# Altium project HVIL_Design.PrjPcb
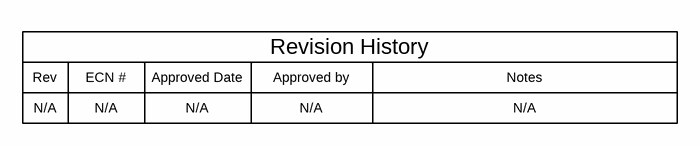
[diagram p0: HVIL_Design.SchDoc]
TID: N/A; TechSupport: http://www.ti.com/support; SCH_Rev: E1; PRJ_Title: Change in menu Project|Project Options|Parameters; PRJ_Number: TIDA-020069; PRJ_Engineer: Enter name of project lead; PRJ_Customer: Public Release; PCB_Rev: E1; PCB_Layout: Who did the Layout?; CopyrightYear: 2018
4 sheets, 99 parts. Net scope: global (net labels, ports and power ports of the same name join across sheets).
Board file: HVIL_Design.PcbDoc
Sheets:
  HVIL_Design.SchDoc
  HVIL_Design_BlankSheet.SchDoc
  HVIL_Design_Hardware.SchDoc
  HVIL_Design_Schematic.SchDoc

## Sheet HVIL_Design.SchDoc
size 431 x 279 mm; Date: Not shown in title block; ApprovedBy: Not shown in title block; CheckedBy: Not shown in title block; Author: Not shown in title block; CompanyName: Not shown in title block; Engineer: Not shown in title block; Organization: Not shown in title block; Address1: Not shown in title block; Address2: Not shown in title block; Address3: Not shown in title block; Address4: Not shown in title block; DocumentNumber: 1; Revision: Use project parameter SCH_Rev; SheetNumber: 1; SheetTotal: 4; PageSetup: Record=PageOptions¦CenterHorizontal=True¦CenterVertical=True¦PrintScale=1.00¦XCorrection=1.00¦YCorrection=1.00¦PrintKind=0¦BorderSize=5000000¦LeftOffset=0¦BottomOffset=0¦Orientation=2¦PaperLength=1000¦PaperWidth=1000¦Scale=100¦PaperSource=15¦PrintQuality=600¦MediaType=1¦DitherType=10¦PaperKind=Letter¦PrintScaleMode=1

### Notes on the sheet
- Rev
- N/A
- ECN #
- Approved Date
- Approved by
- Revision History
- Notes

## Sheet HVIL_Design_BlankSheet.SchDoc
size 431 x 279 mm; Date: Not shown in title block; ApprovedBy: Not shown in title block; CheckedBy: Not shown in title block; Author: Not shown in title block; CompanyName: Not shown in title block; Engineer: Not shown in title block; Organization: Not shown in title block; Address1: Not shown in title block; Address2: Not shown in title block; Address3: Not shown in title block; Address4: Not shown in title block; DocumentNumber: 1; Revision: Use project parameter SCH_Rev; SheetNumber: 2; SheetTotal: 4; PageSetup: Record=PageOptions¦CenterHorizontal=True¦CenterVertical=True¦PrintScale=1.00¦XCorrection=1.00¦YCorrection=1.00¦PrintKind=0¦BorderSize=5000000¦LeftOffset=0¦BottomOffset=0¦Orientation=2¦PaperLength=1000¦PaperWidth=1000¦Scale=100¦PaperSource=15¦PrintQuality=600¦MediaType=1¦DitherType=10¦PaperKind=Letter¦PrintScaleMode=1
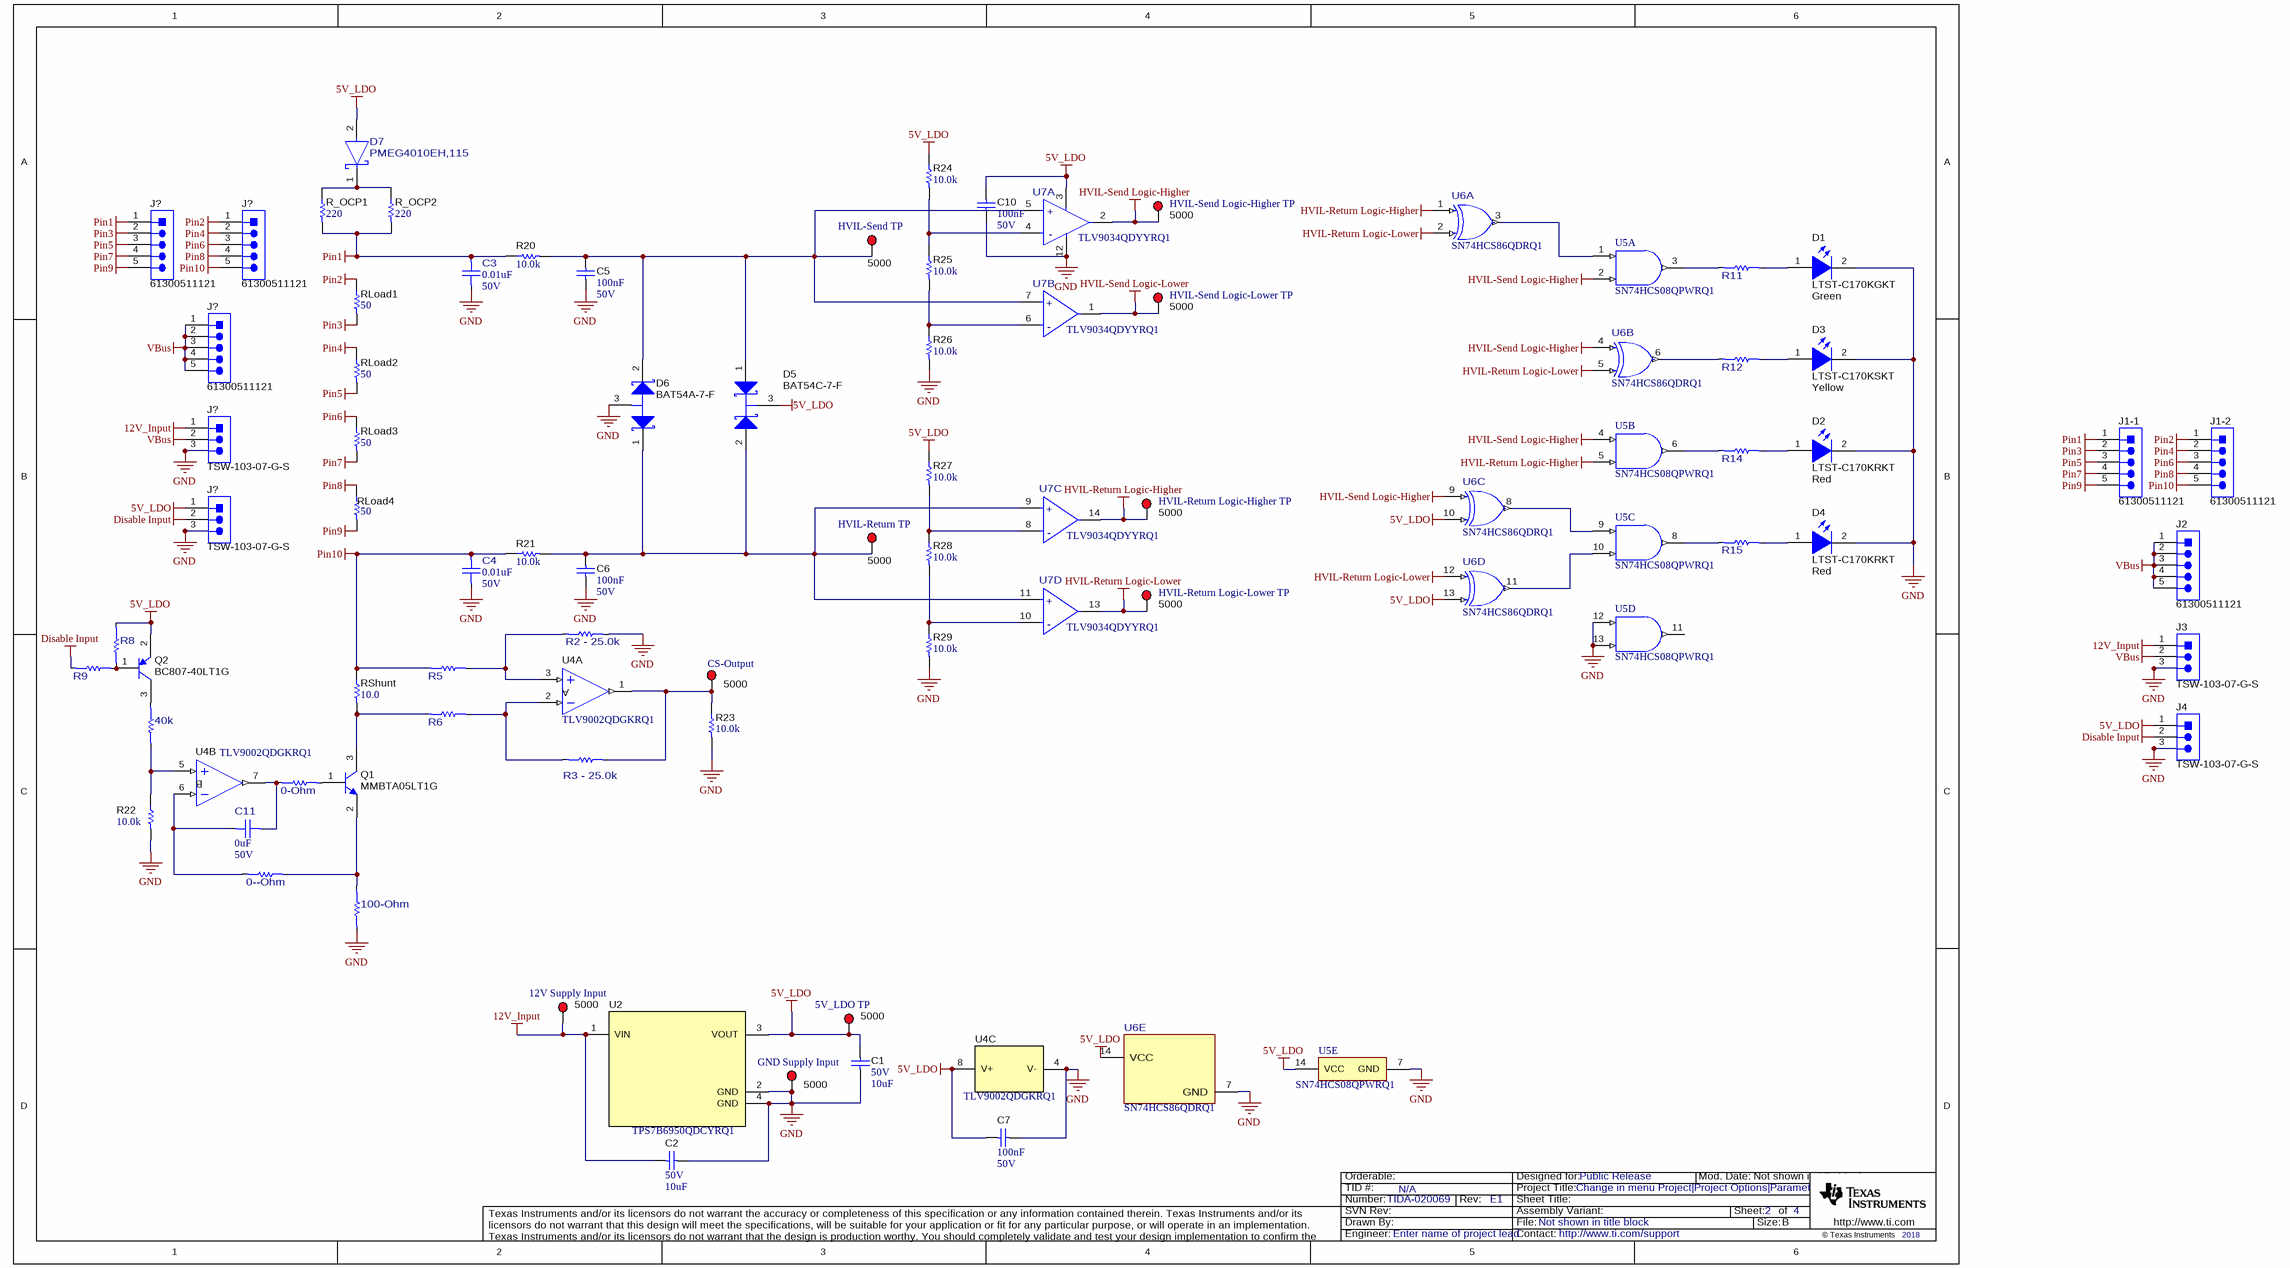
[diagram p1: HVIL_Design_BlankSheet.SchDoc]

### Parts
(Parts that share a designator on the sheet are numbered #1, #2 ... from top to bottom, then left to right.)
0--Ohm  PCAN0805E1000BST5  [FP-PCAN0805E1000BST5_0805-MFG]  (value not drawn)
0-Ohm  PCAN0805E1000BST5  [FP-PCAN0805E1000BST5_0805-MFG]  (value not drawn)
5V_LDO_TP  5000  [Keystone5000]
12V_Supply_Input  5000  [Keystone5000]
40k  PCAN0805E1001BST5  [FP-PCAN0805E1001BST5_0805-MFG]  (value not drawn)
100-Ohm  PCAN0805E1000BST5  [FP-PCAN0805E1000BST5_0805-MFG]  (value not drawn)
C1  VDC_V: 50V  ValueDisplayed: 10uF  [1206_180]  (hidden comment: CL31B106KBHNNNE)
C2  VDC_V: 50V  ValueDisplayed: 10uF  [1206_180]  (hidden comment: CL31B106KBHNNNE)
C3  ValueDisplayed: 0.01uF  VDC_V: 50V  [FP-08055F103K4T2A_0805-MFG]  (hidden comment: 08055F103K4T2A)
C4  ValueDisplayed: 0.01uF  VDC_V: 50V  [FP-08055F103K4T2A_0805-MFG]  (hidden comment: 08055F103K4T2A)
C5  Cap_F: 100nF  VDC_V: 50V  [0805_HV]  (hidden comment: GCM21BR71H104KA37K)
C6  Cap_F: 100nF  VDC_V: 50V  [0805_HV]  (hidden comment: GCM21BR71H104KA37K)
C7  Cap_F: 100nF  VDC_V: 50V  [0805_HV]  (hidden comment: GCM21BR71H104KA37K)
C10  Cap_F: 100nF  VDC_V: 50V  [0805_HV]  (hidden comment: GCM21BR71H104KA37K)
C11  ValueDisplayed: 0uF  VDC_V: 50V  [FP-08055F103K4T2A_0805-MFG]  (hidden comment: 08055F103K4T2A)
CS-Output  5000  [Keystone5000]
D1  LTST-C170KGKT  value Green  [LTST-C170KGKT_Green]
D2  LTST-C170KRKT  value Red  [LED_LTST-C170_Red]
D3  LTST-C170KSKT  value Yellow  [LED_LTST-C170]
D4  LTST-C170KRKT  value Red  [LED_LTST-C170_Red]
D5  BAT54C-7-F  [SOT-23]
D6  BAT54A-7-F  [SOT-23]
D7  PMEG4010EH,115  [FP-PMEG4010EH_115_SOD123F-MFG]
GND_Supply_Input  5000  [Keystone5000]
HVIL-Return_Logic-Higher_TP  5000  [Keystone5000]
HVIL-Return_Logic-Lower_TP  5000  [Keystone5000]
HVIL-Return_TP  5000  [Keystone5000]
HVIL-Send_Logic-Higher_TP  5000  [Keystone5000]
HVIL-Send_Logic-Lower_TP  5000  [Keystone5000]
HVIL-Send_TP  5000  [Keystone5000]
J1-1  61300511121  [Wurth_61300511121]
J1-2  61300511121  [Wurth_61300511121]
J2  61300511121  [Wurth_61300511121]
J3  TSW-103-07-G-S  [TSW-103-07-G-S]
J4  TSW-103-07-G-S  [TSW-103-07-G-S]
J?#1  61300511121  [Wurth_61300511121]
J?#2  61300511121  [Wurth_61300511121]
J?#3  61300511121  [Wurth_61300511121]
J?#4  TSW-103-07-G-S  [TSW-103-07-G-S]
J?#5  TSW-103-07-G-S  [TSW-103-07-G-S]
Q1  MMBTA05LT1G  [SOT-23]
Q2  BC807-40LT1G  [SOT-23]
R2_-_25.0k  PCAN0805E1001BST5  [FP-PCAN0805E1001BST5_0805-MFG]  (value not drawn)
R3_-_25.0k  PCAN0805E1001BST5  [FP-PCAN0805E1001BST5_0805-MFG]  (value not drawn)
R5  PCAN0805E1001BST5  [FP-PCAN0805E1001BST5_0805-MFG]  (value not drawn)
R6  PCAN0805E1001BST5  [FP-PCAN0805E1001BST5_0805-MFG]  (value not drawn)
R8  PCAN0805E1001BST5  [FP-PCAN0805E1001BST5_0805-MFG]  (value not drawn)
R9  PCAN0805E1001BST5  [FP-PCAN0805E1001BST5_0805-MFG]  (value not drawn)
R11  PCAN0805E1001BST5  [FP-PCAN0805E1001BST5_0805-MFG]  (value not drawn)
R12  PCAN0805E1001BST5  [FP-PCAN0805E1001BST5_0805-MFG]  (value not drawn)
R14  PCAN0805E1001BST5  [FP-PCAN0805E1001BST5_0805-MFG]  (value not drawn)
R15  PCAN0805E1001BST5  [FP-PCAN0805E1001BST5_0805-MFG]  (value not drawn)
R20  ValueDisplayed: 10.0k  [0805_HV]  (hidden comment: MCU0805MD1002BP100)
R21  ValueDisplayed: 10.0k  [0805_HV]  (hidden comment: MCU0805MD1002BP100)
R22  ValueDisplayed: 10.0k  [0805_HV]  (hidden comment: MCU0805MD1002BP100)
R23  ValueDisplayed: 10.0k  [0805_HV]  (hidden comment: MCU0805MD1002BP100)
R24  ValueDisplayed: 10.0k  [0805_HV]  (hidden comment: MCU0805MD1002BP100)
R25  ValueDisplayed: 10.0k  [0805_HV]  (hidden comment: MCU0805MD1002BP100)
R26  ValueDisplayed: 10.0k  [0805_HV]  (hidden comment: MCU0805MD1002BP100)
R27  ValueDisplayed: 10.0k  [0805_HV]  (hidden comment: MCU0805MD1002BP100)
R28  ValueDisplayed: 10.0k  [0805_HV]  (hidden comment: MCU0805MD1002BP100)
R29  ValueDisplayed: 10.0k  [0805_HV]  (hidden comment: MCU0805MD1002BP100)
R_OCP1  ValueDisplayed: 220  [1206]  (hidden comment: CRCW1206220RJNEA)
R_OCP2  ValueDisplayed: 220  [1206]  (hidden comment: CRCW1206220RJNEA)
RLoad1  ValueDisplayed: 50  [0603]  (hidden comment: FC0603E50R0BTBST1)
RLoad2  ValueDisplayed: 50  [0603]  (hidden comment: FC0603E50R0BTBST1)
RLoad3  ValueDisplayed: 50  [0603]  (hidden comment: FC0603E50R0BTBST1)
RLoad4  ValueDisplayed: 50  [0603]  (hidden comment: FC0603E50R0BTBST1)
RShunt  ValueDisplayed: 10.0  [0805_HV]  (hidden comment: PATT0805E10R0BGT1)
U2  TPS7B6950QDCYRQ1  [DCY0004A_N]
U4  PartNumber: TLV9002QDGKRQ1  [DGK0008A_N]  (hidden comment: TLV9002QDRQ1)  (parts A,B,C of 3)
U5  SN74HCS08QPWRQ1  [PW0014A_N]  (parts A,B,C,D,E of 5)
U6  PartNumber: SN74HCS86QDRQ1  [D0014A-MFG]  (hidden comment: SN74HCS86DR)  (parts A,B,C,D,E of 5)
U7  TLV9034QDYYRQ1  [DYY0014A-MFG]  (parts A,B,C,D of 4)

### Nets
5V_LDO: 5V_LDO_TP.1 C1.2 C7.1 C10.1 D5.3(K) D7.2(ANODE) J4.1 J?#5.1 Q2.2(E) R8.1 R24.1 R27.1 U2.3(VOUT) U4.8(V+) U5.14(VCC) U6.10(3B) U6.13(4B) U6.14(VCC) U7.3(V+)
12V_Input: 12V_Supply_Input.1 C2.2 J3.1 J?#4.1 U2.1(VIN)
Disable Input: J4.2 J?#5.2 R9.1
GND: 100-Ohm.2 C1.1 C2.1 C3.2 C4.2 C5.1 C6.1 C7.2 C10.2 D1.2(K) D2.2(K) D3.2(K) D4.2(K) D6.3(A) GND_Supply_Input.1 J3.3 J4.3 J?#4.3 J?#5.3 R2_-_25.0k.2 R22.2 R23.2 R26.2 R29.2 U2.2(GND) U2.4(GND) U4.4(V-) U5.7(GND) U5.12(4A) U5.13(4B) U6.7(GND) U7.12(V-)
HVIL-Return Logic-Higher: HVIL-Return_Logic-Higher_TP.1 U5.5(2B) U6.1(1A) U7.14(OUT3)
HVIL-Return Logic-Lower: HVIL-Return_Logic-Lower_TP.1 U6.2(1B) U6.5(2B) U6.12(4A) U7.13(OUT4)
HVIL-Send Logic-Higher: HVIL-Send_Logic-Higher_TP.1 U5.2(1B) U5.4(2A) U6.4(2A) U6.9(3A) U7.2(OUT1)
HVIL-Send Logic-Lower: HVIL-Send_Logic-Lower_TP.1 U7.1(OUT2)
Pin1: C3.1 J1-1.1 J?#1.1 R20.1 R_OCP1.2 R_OCP2.2
Pin2: J1-2.1 J?#2.1 RLoad1.1
Pin3: J1-1.2 J?#1.2 RLoad1.2
Pin4: J1-2.2 J?#2.2 RLoad2.1
Pin5: J1-1.3 J?#1.3 RLoad2.2
Pin6: J1-2.3 J?#2.3 RLoad3.1
Pin7: J1-1.4 J?#1.4 RLoad3.2
Pin8: J1-2.4 J?#2.4 RLoad4.1
Pin9: J1-1.5 J?#1.5 RLoad4.2
Pin10: C4.1 J1-2.5 J?#2.5 R5.1 R21.1 RShunt.1
VBus: J2.1 J2.2 J2.3 J2.4 J2.5 J3.2 J?#3.1 J?#3.2 J?#3.3 J?#3.4 J?#3.5 J?#4.2
Net0--Ohm_1: 0--Ohm.1 100-Ohm.1 Q1.2(E)
Net0--Ohm_2: 0--Ohm.2 C11.2 U4.6(IN-)
Net0-Ohm_1: 0-Ohm.1 Q1.1(B)
Net0-Ohm_2: 0-Ohm.2 C11.1 U4.7(OUT)
Net40k_1: 40k.1 Q2.3(C)
Net40k_2: 40k.2 R22.1 U4.5(IN+)
NetC5_2: C5.2 D5.1(A1) D6.2(K2) HVIL-Send_TP.1 R20.2 U7.5(IN1+) U7.7(IN2+)
NetC6_2: C6.2 D5.2(A2) D6.1(K1) HVIL-Return_TP.1 R21.2 U7.9(IN3+) U7.11(IN4+)
NetCS-Output_1: CS-Output.1 R3_-_25.0k.2 R23.1 U4.1(OUT)
NetD1_1: D1.1(A) R11.2
NetD2_1: D2.1(A) R14.2
NetD3_1: D3.1(A) R12.2
NetD4_1: D4.1(A) R15.2
NetD7_1: D7.1(CATHODE) R_OCP1.1 R_OCP2.1
NetQ1_3: Q1.3(C) R6.1 RShunt.2
NetQ2_1: Q2.1(B) R8.2 R9.2
NetR2_-_25.0k_1: R2_-_25.0k.1 R5.2 U4.3(IN+)
NetR3_-_25.0k_1: R3_-_25.0k.1 R6.2 U4.2(IN-)
NetR11_1: R11.1 U5.3(1Y)
NetR12_1: R12.1 U6.6(2Y)
NetR14_1: R14.1 U5.6(2Y)
NetR15_1: R15.1 U5.8(3Y)
NetR24_2: R24.2 R25.1 U7.4(IN1-)
NetR25_2: R25.2 R26.1 U7.6(IN2-)
NetR27_2: R27.2 R28.1 U7.8(IN3-)
NetR28_2: R28.2 R29.1 U7.10(IN4-)
NetU5_1: U5.1(1A) U6.3(1Y)
NetU5_9: U5.9(3A) U6.8(3Y)
NetU5_10: U5.10(3B) U6.11(4Y)

Not connected (* = marked no-connect by the designer): U5 11(4Y)

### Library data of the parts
0--Ohm 0-Ohm 100-Ohm = CMP-0091946-1: 100 Ohms ±0.1% 1W Chip Resistor 0805 (2012 Metric) Flame Proof, Moisture Resistant, Safety Thin Film; Manufacturer: Vishay; SizeZ_mm: 0.018inch; Value: 100; VDC_V: 100V; TempCo: 25ppm/°C; AEC Qualified: No
5V_LDO_TP 12V_Supply_Input CS-Output GND_Supply_Input HVIL-Return_Logic-Higher_TP HVIL-Return_Logic-Lower_TP HVIL-Return_TP HVIL-Send_Logic-Higher_TP HVIL-Send_Logic-Lower_TP HVIL-Send_TP = CMP-0055137-2: Test Point, Miniature, Red, TH; Manufacturer: Keystone Electronics; Green_REACh: Passed; Green_Lifecycle: Active; ContactFinish: Silver; CNHeader: FALSE; CT: TRUE
40k R2_-_25.0k R5 R6 R8 R9 R11 R12 R14 R15 = CMP-0089213-1: 1 kOhms ±0.1% 1W Chip Resistor 0805 (2012 Metric) Flame Proof, Moisture Resistant, Safety Thin Film; Manufacturer: Vishay; TempCo: 25ppm/°C; AEC Qualified: No; SizeZ_mm: 0.018inch; Res_ohm: 1k; VDC_V: 100V
C1 C2 = CMP-0008802-2: CAP, CERM, 10 uF, 50 V, +/- 10%, X7R, 1206; Manufacturer: Samsung; TaMin_C: -55°C; Polarized: N; SizeAreaWB_mm2: 10.92; Value1: Unknown; U/M: EA; Value: 10uF; TaMax_C: 125°C; SizeZ_mm: 1.8; SizeX_mm: 3.2; SizeY_mm: 1.6; Cap_Case: 1206; SizeArea_mm2: 5.12; Cap_F: 10µF; AEC Category: Q200
C3 C4 C11 = CMP-0089555-2: CAP, CERM, 10000 pF, 50 V,+/- 10%, X8R, AEC-Q200 Grade 0, 0805; Manufacturer: AVX; AEC Grade: Grade 0; Cap_F: 10nF; TempCo: 15%; SizeZ_mm: 0.94mm; AEC Qualified: Yes
C5-C7 C10 = CMP-0008021-2: CAP, CERM, 0.1 uF, 50 V, +/- 10%, X7R, AEC-Q200 Grade 1, 0805; Manufacturer: MuRata; TaMin_C: -55°C; Polarized: N; SizeAreaWB_mm2: 6.75; Value1: Unknown; U/M: EA; Value: 0.1uF; TaMax_C: 125°C; SizeZ_mm: 1.45; SizeX_mm: 2; SizeY_mm: 1.25; Cap_Case: 0805; SizeArea_mm2: 2.5; AEC Qualified: Y; AEC Grade: 1; AEC Category: Q200
D1 = CMP-0002888-2: LED, Green, SMD; Manufacturer: Lite-On; Value1: W; Vf_V: 2V; Type: AlInGaP; Io_A: 20mA
D2 D4 = CMP-0002829-3: LED, Red, SMD; Manufacturer: Lite-On; SizeZ_mm: 1.2; Value1: W; SizeY_mm: 1.25; Value2: 2V; SizeArea_mm2: 2.5; SizeX_mm: 2; SizeAreaWB_mm2: 6.75; Io_A: 20mA; Type: AlInGaP
D3 = CMP-0002862-2: LED, Yellow , SMD; Manufacturer: Lite-On; SizeY_mm: 1.25; SizeZ_mm: 1.2; SizeX_mm: 2; Vf_V: 2V; Type: AlInGaP; SizeAreaWB_mm2: 6.75; Value1: W; Io_A: 20mA; SizeArea_mm2: 2.5
D5 = CMP-0028453-2: Diode, Schottky, 30 V, 0.2 A, SOT-23; Manufacturer: Diodes Inc.; Vr_V: 30V; Green_Lifecycle: Active; Vf_V: 650mV; Value: 30V; SizeZ_mm: 1.1; SizeAreaWB_mm2: 14; TJmax_C: 125°C; Io_A: 200mA; Value2: 0.65V; SizeY_mm: 3; AEC Category: Q101; SizeX_mm: 2.5; Green_REACh: Passed; Value1: 0.2A; SizeArea_mm2: 7.5
D6 = CMP-0028452-2: Diode, Schottky, 30 V, 0.2 A, SOT-23; Manufacturer: Diodes Inc.; Vf_V: 650mV; Green_Lifecycle: Active; TJmax_C: 125°C; Green_REACh: Passed; Io_A: 200mA; Value2: 0.65V; AEC Category: Q101; Vr_V: 30V; Value: 30V; SizeArea_mm2: 7.5; SizeAreaWB_mm2: 14; SizeZ_mm: 1.1; Value1: 0.2A; SizeX_mm: 2.5; SizeY_mm: 3
D7 = CMP-0091342-2: Diode Schottky 40V 1A (DC) Surface Mount SOD-123F; Manufacturer: Nexperia; AEC Qualified: Yes; ValueDisplayed: 43pF; TJmax_C: 150°C; TaMin_C: -65°C; AEC Grade: Grade 0; TaMax_C: +150°C; SizeZ_mm: 1.2mm; Peak Reverse Current: 30uA; Max Surge Forward Current: 9A; AEC Category: Q101
J1-1 J1-2 J2 J?#1-J?#3 = CMP-0084909-1: Header, 2.54mm, 5x1, Gold, TH; Manufacturer: Wurth Elektronik; Pitch_mm: 2.54; Gender: Male; Row_Count: 1; Shrouded: N; Current_A: 3A; Voltage_V: 250V
J3 J4 J?#4 J?#5 = CMP-0075407-2: Header, 100mil, 3x1, Gold, TH; Manufacturer: Samtec; Pitch_mm: 2.54; Cert_VDE: N; Gender: Male; Cert_CSA: Y; Voltage_V: 550V; Green_REACh: Passed; Current_A: 6.3A; Green_Lifecycle: Active; Row_Count: 1
Q1 = CMP-0000488-2: Transistor, NPN, 60 V, 0.5 A, AEC-Q101, SOT-23; Manufacturer: ON Semiconductor; TaMax_C: 150°C; Value1: 0.5 A; Vcesat1_V: 250mV; SizeX_mm: 2.5; SizeY_mm: 3; TaMin_C: -55°C; IcRated_A: 500mA; CompType: BJT; SizeZ_mm: 1.1; AEC Qualified: Y; Value: 60 V; SizeArea_mm2: 7.5; NPN: 1; Vceo_V: 60V; PNP: 0; AEC Category: Q101; SizeAreaWB_mm2: 14; U/M: EA
Q2 = CMP-0000367-2: Transistor, PNP, 45 V, 0.5 A, AEC-Q101, SOT-23; Manufacturer: ON Semiconductor; TaMax_C: 150°C; Value2: 600; Value1: 0.5 A; Vcesat1_V: 700mV; SizeX_mm: 2.5; SizeY_mm: 3; TaMin_C: -55°C; IcRated_A: 500mA; CompType: BJT; SizeZ_mm: 1.1; AEC Qualified: Y; Value: 45 V; SizeArea_mm2: 7.5; NPN: 0; Vceo_V: 45V; PNP: 1; AEC Category: Q101; SizeAreaWB_mm2: 14; U/M: EA
R3_-_25.0k = CMP-0089213-1: 25 kOhms ±0.1% 1W Chip Resistor 0805 (2012 Metric) Flame Proof, Moisture Resistant, Safety Thin Film; Manufacturer: Vishay; TempCo: 25ppm/°C; AEC Qualified: No; SizeZ_mm: 0.018inch; Res_ohm: 1k; VDC_V: 100V
R20-R29 = CMP-0018838-2: RES, 10.0 k, 0.1%, 0.2 W, AEC-Q200 Grade 0, 0805; Manufacturer: Vishay/Beyschlag; Power_W: 200mW; TempCo: 25 ppm/C; Value_Code: 10k0; U/M: EA; Value: 10.0k; EIA_Code: E192; Res_ohm: 10k; SizeX_mm: 2; SizeY_mm: 1.25; SizeZ_mm: 1.45; Value2: 0.2W; SizeArea_mm2: 2.5; AEC Qualified: Y; VDC_V: 150V; AEC Grade: 0; AEC Category: Q200
R_OCP1 R_OCP2 = CMP-0018629-3: RES, 220, 5%, 0.25 W, AEC-Q200 Grade 0, 1206; Manufacturer: Vishay-Dale; Power_W: 250mW; TempCo: 200 ppm/C; Value_Code: 220R; Value: 220; EIA_Code: E24; SizeX_mm: 3.2; SizeY_mm: 1.6; SizeZ_mm: 1.35; Value2: 0.25W; SizeArea_mm2: 5.12; AEC Qualified: Y; VDC_V: 200V; AEC Category: Q200; AEC Grade: 0
RLoad1-RLoad4 = CMP-0023387-3: RES, 50, 0.1%, 0.125 W, 0603; Manufacturer: Vishay Thin Film; Power_W: 125mW; TempCo: 25 ppm/C; Value_Code: 50R0; U/M: EA; Value: 50; SizeX_mm: 1.6; SizeY_mm: 0.8; SizeZ_mm: 1; Value2: 0.125W; SizeArea_mm2: 1.28; AEC Qualified: N; VDC_V: 50V; AEC Category: Q200
RShunt = CMP-0018841-2: RES, 10.0, 0.1%, 0.2 W, AEC-Q200 Grade 0, 0805; Manufacturer: Vishay Thin Film; Power_W: 200mW; TempCo: 25 ppm/C; Value_Code: 10R0; U/M: EA; Value: 10.0; EIA_Code: E192; Res_ohm: 10; SizeX_mm: 2; SizeY_mm: 1.25; SizeZ_mm: 1.45; Value2: 0.2W; SizeArea_mm2: 2.5; AEC Qualified: Y; AEC Grade: 0; AEC Category: Q200
U2 = CMP-0077337-1: Automotive High-Voltage Ultra-Low IQ Low-Dropout Regulator/Fixed 5-V Output Voltage, DCY0004A (SOT-223-4); Manufacturer: Texas Instruments; SizeAreaWB_mm2: 76.5; SizeArea_mm2: 45.5; SizeZ_mm: 1.8; Green_REACh: Passed; SizeY_mm: 6.5; Green_Lifecycle: Active; U/M: EA; CompType: IC; SizeX_mm: 7
U4 = CMP-0084063-1: 10-MHz, Low-Noise, RRIO, CMOS Operational Amplifier for Cost-Sensitive Systems, DGK0008A (VSSOP-8); Manufacturer: Texas Instruments; Alternate PartNumber: TLV9062IDGKT; Rating: Catalog; SizeAreaWB_mm2: 23.6; SizeArea_mm2: 14.7; AEC Qualified: N; AEC Category: Q200; SizeZ_mm: 1.1; SizeY_mm: 3; CompType: IC; SizeX_mm: 4.9
U5 = CMP-0860019-1: QUADRUPLE 2-INPUT POSITIVE-AND GATE, PW0014A (TSSOP-14); Alternate Manufacturer: Texas Instruments; SizeArea_mm2: 32; SizeZ_mm: 1.2; CompType: IC; AEC Category: Q200; SizeX_mm: 6.4; SizeY_mm: 5; SizeAreaWB_mm2: 58.8; AEC Qualified: Y
U6 = CMP-0094930-1: Quadruple 2-Input XOR Gates with Schmitt-Trigger Inputs; Manufacturer: Texas Instruments; Max Supply Voltage: 6V; TaMin_C: -40°C; AEC Qualified: No; Min Supply Voltage: 2V; SizeZ_mm: 1.75mm; Nominal Supply Current: 0.1uA; Number Of Outputs: 1; Standoff Height: 0.1mm; PositionCount: 4; Propagation Delay: 6ns; Number Of Inputs: 2; TaMax_C: +125°C; TJmax_C: +150°C
U7 = CMP-0091442-1: High-Precision Quad Comparator, Push-Pull output, Automotive, TSOT23-14; Manufacturer: Texas Instruments; Max Supply Voltage: 5.5V; AEC Qualified: Yes; Input Offset Voltage: 0.3mV; TaMax_C: +125°C; TJmax_C: +150°C; Input Bias Current: 0.000005uA; AEC Grade: Grade 1; Nominal Supply Current: 16uA; Standoff Height: 0mm; Voltage Gain: 200V/mV; Min Supply Voltage: 1.65V; SizeZ_mm: 1.1mm; Number Of Channels: 4; Output Current Per Channel: 100mA; TaMin_C: -40°C

## Sheet HVIL_Design_Hardware.SchDoc
size 431 x 279 mm; Date: Not shown in title block; ApprovedBy: Not shown in title block; CheckedBy: Not shown in title block; Author: Not shown in title block; CompanyName: Not shown in title block; Engineer: Not shown in title block; Organization: Not shown in title block; Address1: Not shown in title block; Address2: Not shown in title block; Address3: Not shown in title block; Address4: Not shown in title block; DocumentNumber: 3; Revision: Use project parameter SCH_Rev; SheetNumber: 3; SheetTotal: 4; PageSetup: Record=PageOptions¦CenterHorizontal=True¦CenterVertical=True¦PrintScale=1.00¦XCorrection=1.00¦YCorrection=1.00¦PrintKind=0¦BorderSize=5000000¦LeftOffset=0¦BottomOffset=0¦Orientation=2¦PaperLength=1000¦PaperWidth=1000¦Scale=100¦PaperSource=15¦PrintQuality=600¦MediaType=1¦DitherType=10¦PaperKind=Letter¦PrintScaleMode=1
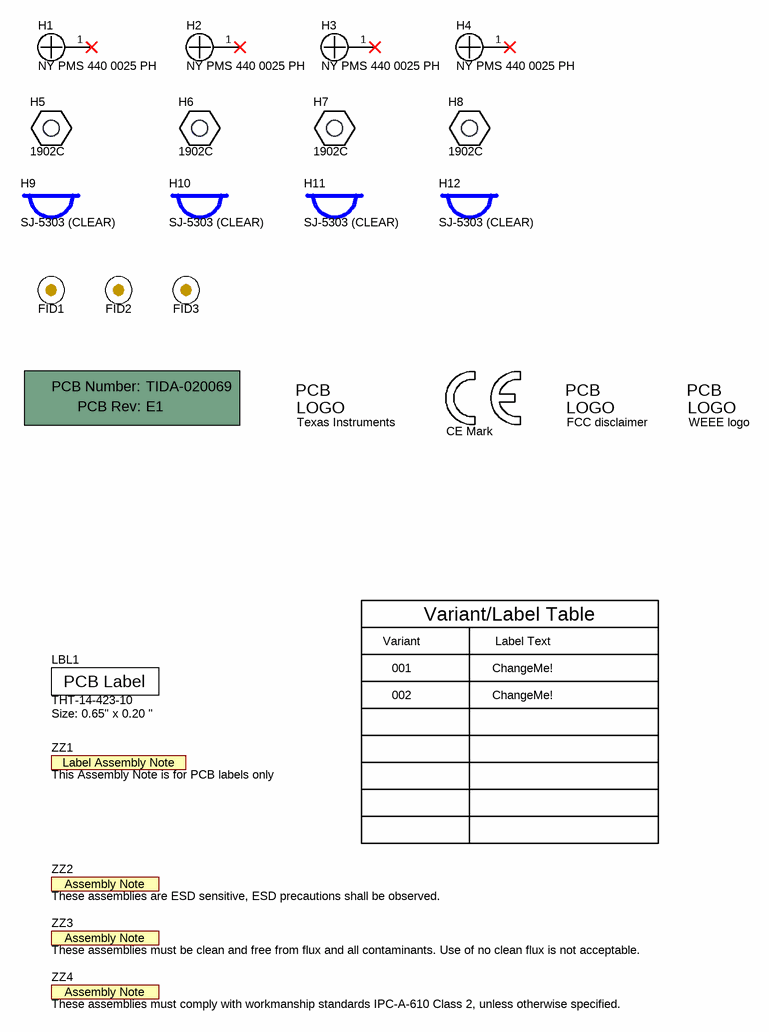
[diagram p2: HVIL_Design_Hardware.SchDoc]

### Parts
!PCB1  Printed Circuit Board  (value not drawn)  (mechanical)
FID1  Fiducial  [Fiducial10-20]  (value not drawn)
FID2  Fiducial  [Fiducial10-20]  (value not drawn)
FID3  Fiducial  [Fiducial10-20]  (value not drawn)
H1  NY PMS 440 0025 PH  [NY PMS 440 0025 PH]
H2  NY PMS 440 0025 PH  [NY PMS 440 0025 PH]
H3  NY PMS 440 0025 PH  [NY PMS 440 0025 PH]
H4  NY PMS 440 0025 PH  [NY PMS 440 0025 PH]
H5  1902C  [Keystone_1902C]
H6  1902C  [Keystone_1902C]
H7  1902C  [Keystone_1902C]
H8  1902C  [Keystone_1902C]
H9  SJ-5303 (CLEAR)  [Bumpon_SJ5003Transparent]
H10  SJ-5303 (CLEAR)  [Bumpon_SJ5003Transparent]
H11  SJ-5303 (CLEAR)  [Bumpon_SJ5003Transparent]
H12  SJ-5303 (CLEAR)  [Bumpon_SJ5003Transparent]
LBL1  THT-14-423-10  Note: Size: 0.65" x 0.20 "  [Label_650x200]
Logo1  CE Mark  [CE_Mark_5mm]  (no BOM)
Logo2  Texas Instruments  [TI_Stacked_Overlay_Small]  (no BOM)
Logo3  FCC disclaimer  [FCC_disclaimer]  (no BOM)
Logo4  WEEE logo  [WEEE_Minimum]  (no BOM)
ZZ1  This Assembly Note is for PCB labels only  [AssemblyNoteLabel]  (no BOM)
ZZ2  These assemblies are ESD sensitive, ESD precautions shall be observed.  [AssemblyNote]  (no BOM)
ZZ3  These assemblies must be clean and free from flux and all contaminants. Use of no clean flux is not acceptable.  [AssemblyNote]  (no BOM)
ZZ4  These assemblies must comply with workmanship standards IPC-A-610 Class 2, unless otherwise specified.  [AssemblyNote]  (no BOM)

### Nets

Not connected (* = marked no-connect by the designer): H1 1*; H2 1*; H3 1*; H4 1*

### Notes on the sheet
- Variant
- Variant/Label Table
- Label Text
- 001
- 002
- ChangeMe!

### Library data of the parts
!PCB1 = CMP-0003618-2: Manufacturer: Any; PartNumber: TIDA-020069
FID1-FID3 = CMP-0077181-1: Fiducial mark.  There is nothing to buy or mount.
H1-H4 = CMP-0003617-1: Machine Screw, Round, #4-40 x 1/4, Nylon, Philips panhead; Manufacturer: B&F Fastener Supply; CompType: Hardware
H5-H8 = CMP-0003610-1: Standoff, Hex, 0.5"L #4-40 Nylon; Manufacturer: Keystone; CompType: Hardware
H9-H12 = CMP-0003620-1: Bumpon, Hemisphere, 0.44 X 0.20, Clear; Manufacturer: 3M
LBL1 = CMP-0003625-1: Thermal Transfer Printable Labels, 0.650" W x 0.200" H - 10,000 per roll; Manufacturer: Brady; CompType: Label
Logo1 = CMP-0074844-1: SymbolCreator: a0412235
Logo2 = CMP-0074838-1: Texas Instrument Corporate Signature; SymbolCreator: a0412235; Lib Reference: TI_Logo; Library Reference: Logo
Logo3 = CMP-0074847-1: FCC_disclaimer; Library Reference: Logo
Logo4 = CMP-0074769-1
ZZ1 = CMP-0003616-3
ZZ2 = CMP-0077236-1
ZZ3 = CMP-0077237-1
ZZ4 = CMP-0077238-1

## Sheet HVIL_Design_Schematic.SchDoc
size 431 x 279 mm; Date: Not shown in title block; ApprovedBy: Not shown in title block; CheckedBy: Not shown in title block; Author: Not shown in title block; CompanyName: Not shown in title block; Engineer: Not shown in title block; Organization: Not shown in title block; Address1: Not shown in title block; Address2: Not shown in title block; Address3: Not shown in title block; Address4: Not shown in title block; DocumentNumber: 2; Revision: Use project parameter SCH_Rev; SheetNumber: 3; SheetTotal: 3; PageSetup: Record=PageOptions¦CenterHorizontal=True¦CenterVertical=True¦PrintScale=1.00¦XCorrection=1.00¦YCorrection=1.00¦PrintKind=0¦BorderSize=5000000¦LeftOffset=0¦BottomOffset=0¦Orientation=2¦PaperLength=1000¦PaperWidth=1000¦Scale=100¦PaperSource=15¦PrintQuality=600¦MediaType=1¦DitherType=10¦PaperKind=Letter¦PrintScaleMode=1

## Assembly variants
001: not fitted FID1 FID2 FID3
